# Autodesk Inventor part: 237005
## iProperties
Created: 2006-08
Part Number: 237005
Material: FSt vz
Description: Federring
Vendor: Autodesk Inc.
Document SubType Name: Modeling
Standard: DIN 127
Designer: I.Baliuc
Standards Organization: DIN
Language: de-DE
Size Designation: A 12
Categories: <MemberInstance Version="R10.0.0"><Categories><Category DisplayName="Schrauben" InternalName="e4da775c-781d-43d5-af7c-5136215cf5a6" Mnemonic="FSTN"><Category Di
Density: 7.86 g/cm^3
Mass: 4.29876 g
Surface Area: 7.22363 cm^2
Volume: 0.546916 cm^3
Abmessung: A12
Author: T.Messerschmitt
Comments: DIN 127 - A 12
Revision Number: 237005
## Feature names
1. Körper [Extrusion]
2. Schnitt [Extrusion]
